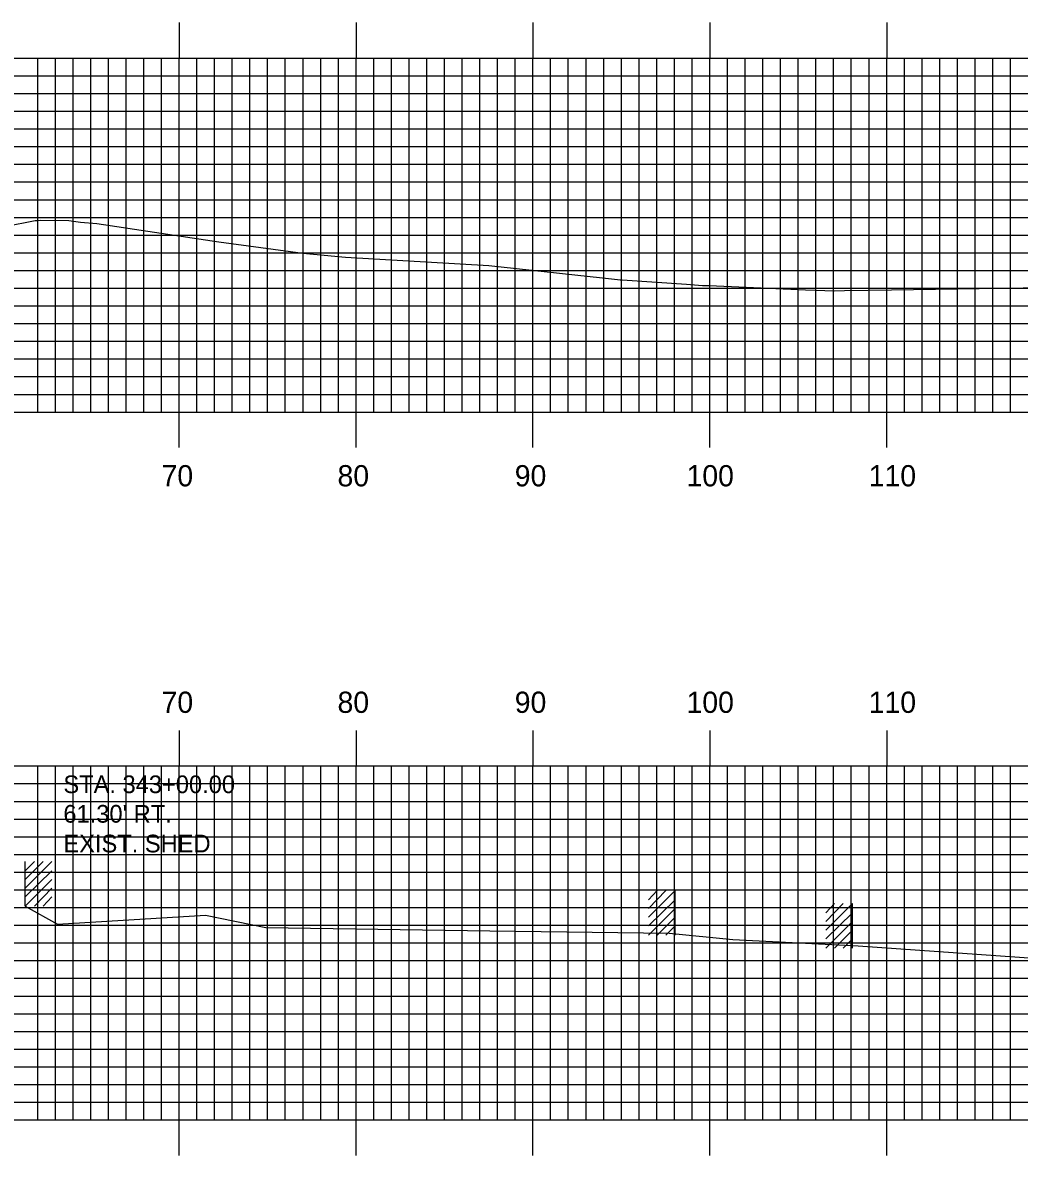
# Model space of a CAD drawing. Extents: x 1825147 to 1825490, y 442591 to 442811.
# Drawn here: x 1825373.5 to 1825429.9, y 442686.7 to 442750.7 of the extents above; entities that cross this region are included whole.
import ezdxf

# ---------------------------------------------------------------- set-up
doc = ezdxf.new("R2010")
doc.units = 0
for name, color, linetype in [('D_Text_Monospaced', 7, 'Continuous'), ('H_V ANNOTATION', 7, 'Continuous'), ('M_Buildings_Rooftop', 7, 'Continuous'), ('MAJOR', 7, 'Continuous'), ('MINOR', 7, 'Continuous'), ('S_Buildings', 7, 'Continuous'), ('S_Roadway_Centerline', 7, 'Continuous')]:
    doc.layers.add(name, color=color, linetype=linetype)

msp = doc.modelspace()

# ---------------------------------------------------------------- linework, layer by layer
at = {"layer": 'M_Buildings_Rooftop'}
for p, q in [((1825408.898, 442700.124), (1825410.408, 442701.633)), ((1825408.898, 442700.616), (1825409.883, 442701.633)), ((1825408.898, 442701.108), (1825409.391, 442701.633)), ((1825408.898, 442699.632), (1825410.408, 442701.108)), ((1825410.408, 442699.107), (1825410.408, 442701.633)), ((1825408.898, 442699.107), (1825410.408, 442700.616)), ((1825418.911, 442699.386), (1825420.42, 442700.895)), ((1825418.911, 442699.878), (1825419.895, 442700.895)), ((1825418.911, 442700.37), (1825419.403, 442700.895)), ((1825420.42, 442698.369), (1825420.42, 442700.895)), ((1825409.391, 442699.107), (1825410.408, 442700.124)), ((1825418.911, 442698.894), (1825420.42, 442700.37)), ((1825418.911, 442698.369), (1825420.42, 442699.878)), ((1825409.883, 442699.107), (1825410.408, 442699.632)), ((1825419.403, 442698.369), (1825420.42, 442699.386)), ((1825419.895, 442698.369), (1825420.42, 442698.894))]:
    msp.add_line(p, q, dxfattribs=at)
at = {"layer": 'MAJOR'}
for p, q in [((1825382.361, 442750.669), (1825382.361, 442748.665)), ((1825392.361, 442750.669), (1825392.361, 442748.665)), ((1825402.361, 442750.669), (1825402.361, 442748.665)), ((1825412.361, 442750.669), (1825412.361, 442748.665)), ((1825422.361, 442750.669), (1825422.361, 442748.665)), ((1825312.361, 442748.665), (1825452.361, 442748.665)), ((1825312.361, 442748.665), (1825452.361, 442748.665)), ((1825382.361, 442728.665), (1825382.361, 442748.665)), ((1825392.361, 442728.665), (1825392.361, 442748.665)), ((1825402.361, 442728.665), (1825402.361, 442748.665)), ((1825412.361, 442728.665), (1825412.361, 442748.665)), ((1825422.361, 442728.665), (1825422.361, 442748.665)), ((1825312.361, 442743.665), (1825452.361, 442743.665)), ((1825312.361, 442738.665), (1825452.361, 442738.665)), ((1825312.361, 442733.665), (1825452.361, 442733.665)), ((1825312.361, 442728.665), (1825452.361, 442728.665)), ((1825312.361, 442728.665), (1825452.361, 442728.665)), ((1825382.361, 442726.661), (1825382.361, 442728.665)), ((1825392.361, 442726.661), (1825392.361, 442728.665)), ((1825402.361, 442726.661), (1825402.361, 442728.665)), ((1825412.361, 442726.661), (1825412.361, 442728.665)), ((1825422.361, 442726.661), (1825422.361, 442728.665)), ((1825382.361, 442710.669), (1825382.361, 442708.665)), ((1825392.361, 442710.669), (1825392.361, 442708.665)), ((1825402.361, 442710.669), (1825402.361, 442708.665)), ((1825412.361, 442710.669), (1825412.361, 442708.665)), ((1825422.361, 442710.669), (1825422.361, 442708.665)), ((1825172.361, 442708.665), (1825452.361, 442708.665)), ((1825172.361, 442708.665), (1825452.361, 442708.665)), ((1825172.361, 442708.665), (1825452.361, 442708.665)), ((1825382.361, 442688.665), (1825382.361, 442708.665)), ((1825382.361, 442688.665), (1825382.361, 442708.665)), ((1825392.361, 442688.665), (1825392.361, 442708.665)), ((1825392.361, 442688.665), (1825392.361, 442708.665)), ((1825402.361, 442688.665), (1825402.361, 442708.665)), ((1825402.361, 442688.665), (1825402.361, 442708.665)), ((1825412.361, 442688.665), (1825412.361, 442708.665)), ((1825412.361, 442688.665), (1825412.361, 442708.665)), ((1825422.361, 442688.665), (1825422.361, 442708.665)), ((1825422.361, 442688.665), (1825422.361, 442708.665)), ((1825172.361, 442703.665), (1825452.361, 442703.665)), ((1825172.361, 442703.665), (1825452.361, 442703.665)), ((1825172.361, 442698.665), (1825452.361, 442698.665)), ((1825172.361, 442698.665), (1825452.361, 442698.665)), ((1825172.361, 442693.665), (1825452.361, 442693.665)), ((1825172.361, 442693.665), (1825452.361, 442693.665)), ((1825172.361, 442688.665), (1825452.361, 442688.665)), ((1825172.361, 442688.665), (1825452.361, 442688.665)), ((1825172.361, 442688.665), (1825452.361, 442688.665)), ((1825382.361, 442686.661), (1825382.361, 442688.665)), ((1825392.361, 442686.661), (1825392.361, 442688.665)), ((1825402.361, 442686.661), (1825402.361, 442688.665)), ((1825412.361, 442686.661), (1825412.361, 442688.665)), ((1825422.361, 442686.661), (1825422.361, 442688.665))]:
    msp.add_line(p, q, dxfattribs=at)
at = {"layer": 'MINOR'}
for p, q in [((1825374.361, 442728.665), (1825374.361, 442748.665)), ((1825375.361, 442728.665), (1825375.361, 442748.665)), ((1825376.361, 442728.665), (1825376.361, 442748.665)), ((1825377.361, 442728.665), (1825377.361, 442748.665)), ((1825378.361, 442728.665), (1825378.361, 442748.665)), ((1825379.361, 442728.665), (1825379.361, 442748.665)), ((1825380.361, 442728.665), (1825380.361, 442748.665)), ((1825381.361, 442728.665), (1825381.361, 442748.665)), ((1825383.361, 442728.665), (1825383.361, 442748.665)), ((1825384.361, 442728.665), (1825384.361, 442748.665)), ((1825385.361, 442728.665), (1825385.361, 442748.665)), ((1825386.361, 442728.665), (1825386.361, 442748.665)), ((1825387.361, 442728.665), (1825387.361, 442748.665)), ((1825388.361, 442728.665), (1825388.361, 442748.665)), ((1825389.361, 442728.665), (1825389.361, 442748.665)), ((1825390.361, 442728.665), (1825390.361, 442748.665)), ((1825391.361, 442728.665), (1825391.361, 442748.665)), ((1825393.361, 442728.665), (1825393.361, 442748.665)), ((1825394.361, 442728.665), (1825394.361, 442748.665)), ((1825395.361, 442728.665), (1825395.361, 442748.665)), ((1825396.361, 442728.665), (1825396.361, 442748.665)), ((1825397.361, 442728.665), (1825397.361, 442748.665)), ((1825398.361, 442728.665), (1825398.361, 442748.665)), ((1825399.361, 442728.665), (1825399.361, 442748.665)), ((1825400.361, 442728.665), (1825400.361, 442748.665)), ((1825401.361, 442728.665), (1825401.361, 442748.665)), ((1825403.361, 442728.665), (1825403.361, 442748.665)), ((1825404.361, 442728.665), (1825404.361, 442748.665)), ((1825405.361, 442728.665), (1825405.361, 442748.665)), ((1825406.361, 442728.665), (1825406.361, 442748.665)), ((1825407.361, 442728.665), (1825407.361, 442748.665)), ((1825408.361, 442728.665), (1825408.361, 442748.665)), ((1825409.361, 442728.665), (1825409.361, 442748.665)), ((1825410.361, 442728.665), (1825410.361, 442748.665)), ((1825411.361, 442728.665), (1825411.361, 442748.665)), ((1825413.361, 442728.665), (1825413.361, 442748.665)), ((1825414.361, 442728.665), (1825414.361, 442748.665)), ((1825415.361, 442728.665), (1825415.361, 442748.665)), ((1825416.361, 442728.665), (1825416.361, 442748.665)), ((1825417.361, 442728.665), (1825417.361, 442748.665)), ((1825418.361, 442728.665), (1825418.361, 442748.665)), ((1825419.361, 442728.665), (1825419.361, 442748.665)), ((1825420.361, 442728.665), (1825420.361, 442748.665)), ((1825421.361, 442728.665), (1825421.361, 442748.665)), ((1825423.361, 442728.665), (1825423.361, 442748.665)), ((1825424.361, 442728.665), (1825424.361, 442748.665)), ((1825425.361, 442728.665), (1825425.361, 442748.665)), ((1825426.361, 442728.665), (1825426.361, 442748.665)), ((1825427.361, 442728.665), (1825427.361, 442748.665)), ((1825428.361, 442728.665), (1825428.361, 442748.665)), ((1825429.361, 442728.665), (1825429.361, 442748.665)), ((1825312.361, 442747.665), (1825452.361, 442747.665)), ((1825312.361, 442746.665), (1825452.361, 442746.665)), ((1825312.361, 442745.665), (1825452.361, 442745.665)), ((1825312.361, 442744.665), (1825452.361, 442744.665)), ((1825312.361, 442742.665), (1825452.361, 442742.665)), ((1825312.361, 442741.665), (1825452.361, 442741.665)), ((1825312.361, 442740.665), (1825452.361, 442740.665)), ((1825312.361, 442739.665), (1825452.361, 442739.665)), ((1825312.361, 442737.665), (1825452.361, 442737.665)), ((1825312.361, 442736.665), (1825452.361, 442736.665)), ((1825312.361, 442735.665), (1825452.361, 442735.665)), ((1825312.361, 442734.665), (1825452.361, 442734.665)), ((1825312.361, 442732.665), (1825452.361, 442732.665)), ((1825312.361, 442731.665), (1825452.361, 442731.665)), ((1825312.361, 442730.665), (1825452.361, 442730.665)), ((1825312.361, 442729.665), (1825452.361, 442729.665)), ((1825374.361, 442688.665), (1825374.361, 442708.665)), ((1825374.361, 442688.665), (1825374.361, 442708.665)), ((1825375.361, 442688.665), (1825375.361, 442708.665)), ((1825375.361, 442688.665), (1825375.361, 442708.665)), ((1825376.361, 442688.665), (1825376.361, 442708.665)), ((1825376.361, 442688.665), (1825376.361, 442708.665)), ((1825377.361, 442688.665), (1825377.361, 442708.665)), ((1825377.361, 442688.665), (1825377.361, 442708.665)), ((1825378.361, 442688.665), (1825378.361, 442708.665)), ((1825378.361, 442688.665), (1825378.361, 442708.665)), ((1825379.361, 442688.665), (1825379.361, 442708.665)), ((1825379.361, 442688.665), (1825379.361, 442708.665)), ((1825380.361, 442688.665), (1825380.361, 442708.665)), ((1825380.361, 442688.665), (1825380.361, 442708.665)), ((1825381.361, 442688.665), (1825381.361, 442708.665)), ((1825381.361, 442688.665), (1825381.361, 442708.665)), ((1825383.361, 442688.665), (1825383.361, 442708.665)), ((1825383.361, 442688.665), (1825383.361, 442708.665)), ((1825384.361, 442688.665), (1825384.361, 442708.665)), ((1825384.361, 442688.665), (1825384.361, 442708.665)), ((1825385.361, 442688.665), (1825385.361, 442708.665)), ((1825385.361, 442688.665), (1825385.361, 442708.665)), ((1825386.361, 442688.665), (1825386.361, 442708.665)), ((1825386.361, 442688.665), (1825386.361, 442708.665)), ((1825387.361, 442688.665), (1825387.361, 442708.665)), ((1825387.361, 442688.665), (1825387.361, 442708.665)), ((1825388.361, 442688.665), (1825388.361, 442708.665)), ((1825388.361, 442688.665), (1825388.361, 442708.665)), ((1825389.361, 442688.665), (1825389.361, 442708.665)), ((1825389.361, 442688.665), (1825389.361, 442708.665)), ((1825390.361, 442688.665), (1825390.361, 442708.665)), ((1825390.361, 442688.665), (1825390.361, 442708.665)), ((1825391.361, 442688.665), (1825391.361, 442708.665)), ((1825391.361, 442688.665), (1825391.361, 442708.665)), ((1825393.361, 442688.665), (1825393.361, 442708.665)), ((1825393.361, 442688.665), (1825393.361, 442708.665)), ((1825394.361, 442688.665), (1825394.361, 442708.665)), ((1825394.361, 442688.665), (1825394.361, 442708.665)), ((1825395.361, 442688.665), (1825395.361, 442708.665)), ((1825395.361, 442688.665), (1825395.361, 442708.665)), ((1825396.361, 442688.665), (1825396.361, 442708.665)), ((1825396.361, 442688.665), (1825396.361, 442708.665)), ((1825397.361, 442688.665), (1825397.361, 442708.665)), ((1825397.361, 442688.665), (1825397.361, 442708.665)), ((1825398.361, 442688.665), (1825398.361, 442708.665)), ((1825398.361, 442688.665), (1825398.361, 442708.665)), ((1825399.361, 442688.665), (1825399.361, 442708.665)), ((1825399.361, 442688.665), (1825399.361, 442708.665)), ((1825400.361, 442688.665), (1825400.361, 442708.665)), ((1825400.361, 442688.665), (1825400.361, 442708.665)), ((1825401.361, 442688.665), (1825401.361, 442708.665)), ((1825401.361, 442688.665), (1825401.361, 442708.665)), ((1825403.361, 442688.665), (1825403.361, 442708.665)), ((1825403.361, 442688.665), (1825403.361, 442708.665)), ((1825404.361, 442688.665), (1825404.361, 442708.665)), ((1825404.361, 442688.665), (1825404.361, 442708.665)), ((1825405.361, 442688.665), (1825405.361, 442708.665)), ((1825405.361, 442688.665), (1825405.361, 442708.665)), ((1825406.361, 442688.665), (1825406.361, 442708.665)), ((1825406.361, 442688.665), (1825406.361, 442708.665)), ((1825407.361, 442688.665), (1825407.361, 442708.665)), ((1825407.361, 442688.665), (1825407.361, 442708.665)), ((1825408.361, 442688.665), (1825408.361, 442708.665)), ((1825408.361, 442688.665), (1825408.361, 442708.665)), ((1825409.361, 442688.665), (1825409.361, 442708.665)), ((1825409.361, 442688.665), (1825409.361, 442708.665)), ((1825410.361, 442688.665), (1825410.361, 442708.665)), ((1825410.361, 442688.665), (1825410.361, 442708.665)), ((1825411.361, 442688.665), (1825411.361, 442708.665)), ((1825411.361, 442688.665), (1825411.361, 442708.665)), ((1825413.361, 442688.665), (1825413.361, 442708.665)), ((1825413.361, 442688.665), (1825413.361, 442708.665)), ((1825414.361, 442688.665), (1825414.361, 442708.665)), ((1825414.361, 442688.665), (1825414.361, 442708.665)), ((1825415.361, 442688.665), (1825415.361, 442708.665)), ((1825415.361, 442688.665), (1825415.361, 442708.665)), ((1825416.361, 442688.665), (1825416.361, 442708.665)), ((1825416.361, 442688.665), (1825416.361, 442708.665)), ((1825417.361, 442688.665), (1825417.361, 442708.665)), ((1825417.361, 442688.665), (1825417.361, 442708.665)), ((1825418.361, 442688.665), (1825418.361, 442708.665)), ((1825418.361, 442688.665), (1825418.361, 442708.665)), ((1825419.361, 442688.665), (1825419.361, 442708.665)), ((1825419.361, 442688.665), (1825419.361, 442708.665)), ((1825420.361, 442688.665), (1825420.361, 442708.665)), ((1825420.361, 442688.665), (1825420.361, 442708.665)), ((1825421.361, 442688.665), (1825421.361, 442708.665)), ((1825421.361, 442688.665), (1825421.361, 442708.665)), ((1825423.361, 442688.665), (1825423.361, 442708.665)), ((1825423.361, 442688.665), (1825423.361, 442708.665)), ((1825424.361, 442688.665), (1825424.361, 442708.665)), ((1825424.361, 442688.665), (1825424.361, 442708.665)), ((1825425.361, 442688.665), (1825425.361, 442708.665)), ((1825425.361, 442688.665), (1825425.361, 442708.665)), ((1825426.361, 442688.665), (1825426.361, 442708.665)), ((1825426.361, 442688.665), (1825426.361, 442708.665)), ((1825427.361, 442688.665), (1825427.361, 442708.665)), ((1825427.361, 442688.665), (1825427.361, 442708.665)), ((1825428.361, 442688.665), (1825428.361, 442708.665)), ((1825428.361, 442688.665), (1825428.361, 442708.665)), ((1825429.361, 442688.665), (1825429.361, 442708.665)), ((1825429.361, 442688.665), (1825429.361, 442708.665)), ((1825172.361, 442707.665), (1825452.361, 442707.665)), ((1825172.361, 442707.665), (1825452.361, 442707.665)), ((1825172.361, 442706.665), (1825452.361, 442706.665)), ((1825172.361, 442706.665), (1825452.361, 442706.665)), ((1825172.361, 442705.665), (1825452.361, 442705.665)), ((1825172.361, 442705.665), (1825452.361, 442705.665)), ((1825172.361, 442704.665), (1825452.361, 442704.665)), ((1825172.361, 442704.665), (1825452.361, 442704.665)), ((1825172.361, 442702.665), (1825452.361, 442702.665)), ((1825172.361, 442702.665), (1825452.361, 442702.665)), ((1825172.361, 442701.665), (1825452.361, 442701.665)), ((1825172.361, 442701.665), (1825452.361, 442701.665)), ((1825172.361, 442700.665), (1825452.361, 442700.665)), ((1825172.361, 442700.665), (1825452.361, 442700.665)), ((1825172.361, 442699.665), (1825452.361, 442699.665)), ((1825172.361, 442699.665), (1825452.361, 442699.665)), ((1825172.361, 442697.665), (1825452.361, 442697.665)), ((1825172.361, 442697.665), (1825452.361, 442697.665)), ((1825172.361, 442696.665), (1825452.361, 442696.665)), ((1825172.361, 442696.665), (1825452.361, 442696.665)), ((1825172.361, 442695.665), (1825452.361, 442695.665)), ((1825172.361, 442695.665), (1825452.361, 442695.665)), ((1825172.361, 442694.665), (1825452.361, 442694.665)), ((1825172.361, 442694.665), (1825452.361, 442694.665)), ((1825172.361, 442692.665), (1825452.361, 442692.665)), ((1825172.361, 442692.665), (1825452.361, 442692.665)), ((1825172.361, 442691.665), (1825452.361, 442691.665)), ((1825172.361, 442691.665), (1825452.361, 442691.665)), ((1825172.361, 442690.665), (1825452.361, 442690.665)), ((1825172.361, 442690.665), (1825452.361, 442690.665)), ((1825172.361, 442689.665), (1825452.361, 442689.665)), ((1825172.361, 442689.665), (1825452.361, 442689.665))]:
    msp.add_line(p, q, dxfattribs=at)
at = {"layer": 'S_Buildings'}
for p, q in [((1825373.659, 442700.742), (1825373.659, 442703.268)), ((1825373.659, 442701.759), (1825375.168, 442703.268)), ((1825373.659, 442702.251), (1825374.676, 442703.268)), ((1825373.659, 442702.743), (1825374.184, 442703.268)), ((1825373.659, 442701.267), (1825375.168, 442702.743)), ((1825373.659, 442700.742), (1825375.168, 442702.251)), ((1825374.184, 442700.742), (1825375.168, 442701.759)), ((1825374.676, 442700.742), (1825375.168, 442701.267))]:
    msp.add_line(p, q, dxfattribs=at)
at = {"layer": 'S_Roadway_Centerline'}
for points in [[(1825372.498, 442739.152), (1825374.22, 442739.482), (1825374.335, 442739.482), (1825374.494, 442739.504), (1825376.115, 442739.487), (1825376.782, 442739.391), (1825377.703, 442739.311), (1825384.607, 442738.279), (1825389.352, 442737.649), (1825391.759, 442737.422), (1825399.858, 442736.939), (1825406.297, 442736.253), (1825407.146, 442736.155), (1825407.293, 442736.139), (1825407.396, 442736.132), (1825411.046, 442735.883), (1825411.955, 442735.822), (1825412.045, 442735.824), (1825412.086, 442735.824), (1825412.323, 442735.811), (1825417.771, 442735.567), (1825419.409, 442735.51), (1825419.971, 442735.529), (1825422.64, 442735.575), (1825435.035, 442735.754)], [(1825373.659, 442700.742), (1825375.488, 442699.72), (1825383.845, 442700.231), (1825387.263, 442699.545), (1825399.92, 442699.349), (1825410.057, 442699.219), (1825413.653, 442698.857), (1825420.747, 442698.508), (1825438.731, 442697.234), (1825442.904, 442697.049), (1825443.732, 442697.051), (1825444.919, 442697.008), (1825452.361, 442696.925)]]:
    msp.add_lwpolyline(points, dxfattribs=at)

# ---------------------------------------------------------------- texts
at = {"layer": 'D_Text_Monospaced'}
for s, height, p in [('STA. 343+00.00', 0.99996, (1825375.814, 442707.129)), ("61.30' RT.", 1, (1825375.814, 442705.461)), ('EXIST. SHED', 0.99996, (1825375.814, 442703.781))]:
    msp.add_text(s, height=height, dxfattribs=at).set_placement(p)
at = {"layer": 'H_V ANNOTATION'}
for s, p in [('70', (1825381.365, 442724.465)), ('80', (1825391.312, 442724.465)), ('90', (1825401.333, 442724.465)), ('100', (1825411.044, 442724.465)), ('110', (1825421.344, 442724.465)), ('70', (1825381.365, 442711.665)), ('80', (1825391.312, 442711.665)), ('90', (1825401.333, 442711.665)), ('100', (1825411.044, 442711.665)), ('110', (1825421.344, 442711.665))]:
    msp.add_text(s, height=1.2, dxfattribs=at).set_placement(p)

doc.saveas('drawing.dxf')
